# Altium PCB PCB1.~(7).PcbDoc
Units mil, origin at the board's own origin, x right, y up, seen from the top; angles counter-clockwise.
Board outline 6000 x 4000 mil, 2 copper layers (Top Layer, Bottom Layer); 6 components, 11 nets, 34 pads, 0 vias.
Unrouted connection lines stored in the file: 16.
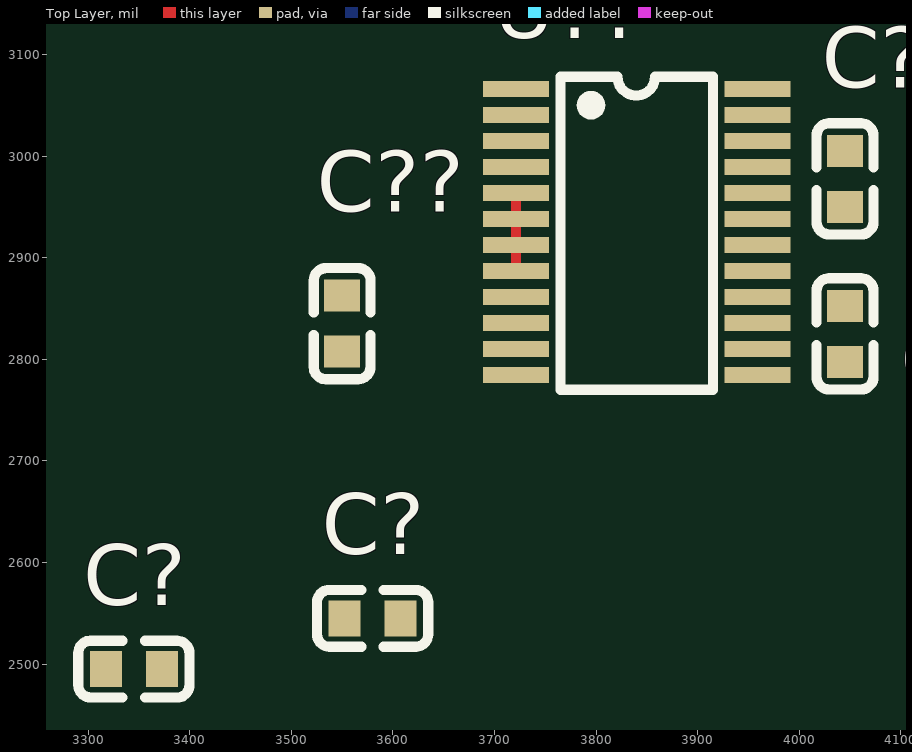
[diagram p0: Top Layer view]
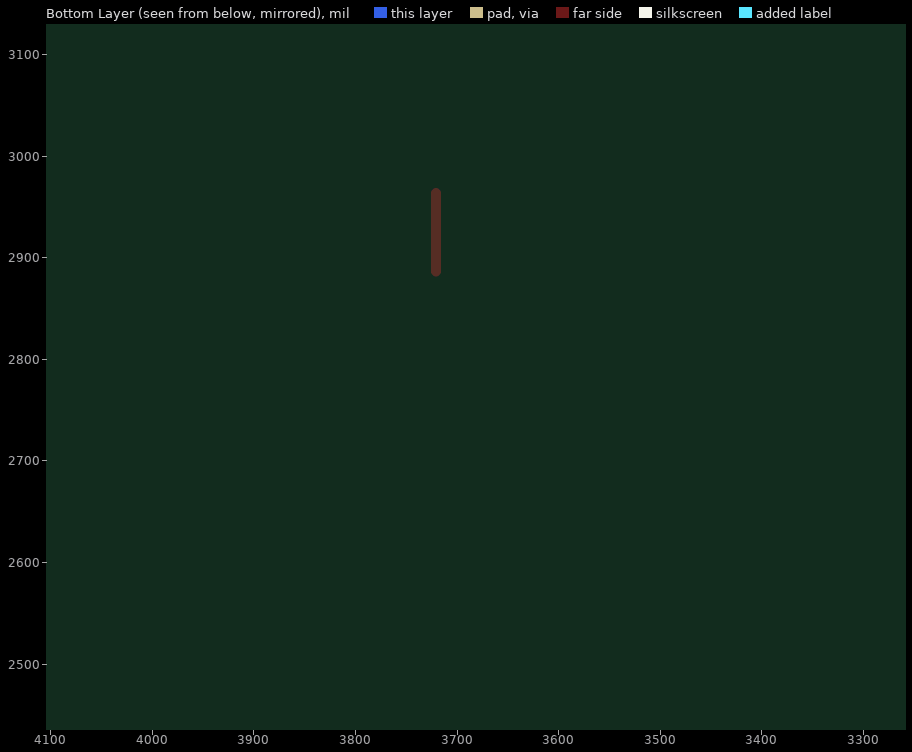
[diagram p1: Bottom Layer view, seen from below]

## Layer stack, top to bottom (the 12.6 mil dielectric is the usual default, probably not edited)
Top Solder: solder mask 0.4, Solder Resist, Dk 3.5
Top Layer: signal copper 1.4
Dielectric 1: dielectric 12.6, FR-4, Dk 4.8
Bottom Layer: signal copper 1.4
Bottom Solder: solder mask 0.4, Solder Resist, Dk 3.5

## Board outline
1000,1000 7000,1000 7000,5000 1000,5000

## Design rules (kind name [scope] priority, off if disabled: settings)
Clearance [All] p1: gap=10 ignorepadtopadclearanceinfootprint=FALSE
PolygonConnect [All] p1: connectstyle=Relief reliefconductorwidth=10 reliefentries=4 polygonreliefangle="90 Angle" airgapwidth=10
RoutingVias [All] p1: holewidth=28 width=50 viastyle="Through Hole" minholewidth=28 minwidth=50 maxholewidth=28 maxwidth=50
SolderMaskExpansion [All] p1: expansion=0 istentingtop=FALSE
SupplyNets "Schematic Supply Nets_3" [InNet('DGND')] p1: voltage=0.000
SupplyNets "Schematic Supply Nets_2" [InNet('+3')] p2: voltage=0.000
SupplyNets "Schematic Supply Nets_1" [InNet('AGND')] p3: voltage=0.000
SupplyNets "Schematic Supply Nets" [InNet('+5')] p4: voltage=0.000
Width [All] p1: maxlimit=10 minlimit=10 preferedwidth=10
30 further rules are at their usual default settings.

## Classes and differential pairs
component class Sheet1: C? C?? U??

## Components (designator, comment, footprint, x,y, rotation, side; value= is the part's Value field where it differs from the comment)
C? "cga0603x7r104k500jt" C0603 4045,2825 r90 top value=100nF
C? "cga0603x7r104k500jt" C0603 3580,2545 r0 top value=100nF
C? "cga0603x7r104k500jt" C0603 3345,2495 r0 top value=100nF
C? "cga0603x7r104k500jt" C0603 4045,2977.56 r90 top value=100nF
C?? "cga0603x7r104k500jt" C0603 3550,2835 r90 top value=100nF
U?? "ads1232ipwr" TSSOP-24_L7.8-W4.4-P0.65-LS6.4-BL 3840,2925 r270 top

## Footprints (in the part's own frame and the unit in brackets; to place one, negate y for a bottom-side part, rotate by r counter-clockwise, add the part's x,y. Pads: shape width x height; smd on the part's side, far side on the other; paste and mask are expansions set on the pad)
C0603 [mm]
  rect 0.8x0.9 smd: 1(-0.7,0) 2(0.7,0)
  silkscreen extent -1.39,-0.71 1.39,0.71
TSSOP-24_L7.8-W4.4-P0.65-LS6.4-BL [mm]
  rect 0.4x1.65 smd: 1(-3.575,-3.023) 2(-2.925,-3.023) 3(-2.275,-3.023) 4(-1.625,-3.023) 5(-0.975,-3.023) 6(-0.325,-3.023) 7(0.325,-3.023) 8(0.975,-3.023) 9(1.625,-3.023) 10(2.275,-3.023) 11(2.925,-3.023) 12(3.575,-3.023) 13(3.575,3.023) 14(2.925,3.023) 15(2.275,3.023) 16(1.625,3.023) 17(0.975,3.023) 18(0.325,3.023) 19(-0.325,3.023) 20(-0.975,3.023) 21(-1.625,3.023) 22(-2.275,3.023) 23(-2.925,3.023) 24(-3.575,3.023)
  silkscreen extent -3.89,-1.91 3.94,1.91

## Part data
C? C? C? C? C??: "容值:100nF;精度:±10%;额定电压:50V;温度系数:X7R;", JLCPCB Part Class="Extended Part", LCSC Part Name="100nF ±10% 50V", Manufacturer=HRE(芯声), ManufacturerPart=CGA0603X7R104K500JT, Temperature Coefficient=X7R, Tolerance=±10%, Voltage Rating=50V
U??: "分辨率(位):24;采样率:10Hz;工作电压:2.7V~5.3V;接口类型:SPI;", Clock Frequency=4.9152MHz；200kHz~8MHz, JLCPCB Part Class="Extended Part", LCSC Part Name="用于桥式传感器的24bit 模数转换器", Manufacturer=TI(德州仪器), ManufacturerPart=ADS1232IPWR, Operating Temperature=-40℃~+105℃, Quiescent Current (Iq)=1.3uA, Temperature Sensors=内置, Voltage - Supply=2.7V~5.3V, Voltage Reference=外置, Voltage Reference Drift=-

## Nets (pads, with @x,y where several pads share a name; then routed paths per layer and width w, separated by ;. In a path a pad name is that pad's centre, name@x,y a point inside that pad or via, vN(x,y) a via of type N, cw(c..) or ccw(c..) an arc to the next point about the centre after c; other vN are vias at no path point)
+3: C?.1@4045,2950 U??.1 U??.19 U??.20
+5: C?.2@3607.56,2545 C?.2@4045,2852.56 U??.16 U??.18
AGND: C?.1@3552.44,2545 C?.1@4045,2797.44 U??.13 U??.14 U??.15 U??.17
AINN1: U??.12
AINP1: U??.11
DGND: C?.2@4045,3005.12 U??.2 U??.5 U??.6 U??.7 U??.8 U??.21 | length 76.8
  Top Layer w10: U??.8 U??.5
DOUT: U??.24
NetC??_1: C??.1 U??.10
NetC??_2: C??.2 U??.9
PDWN: U??.22
SCLK: U??.23
pads on no net: C?.1@3317.44,2495 C?.2@3372.56,2495 U??.3 U??.4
